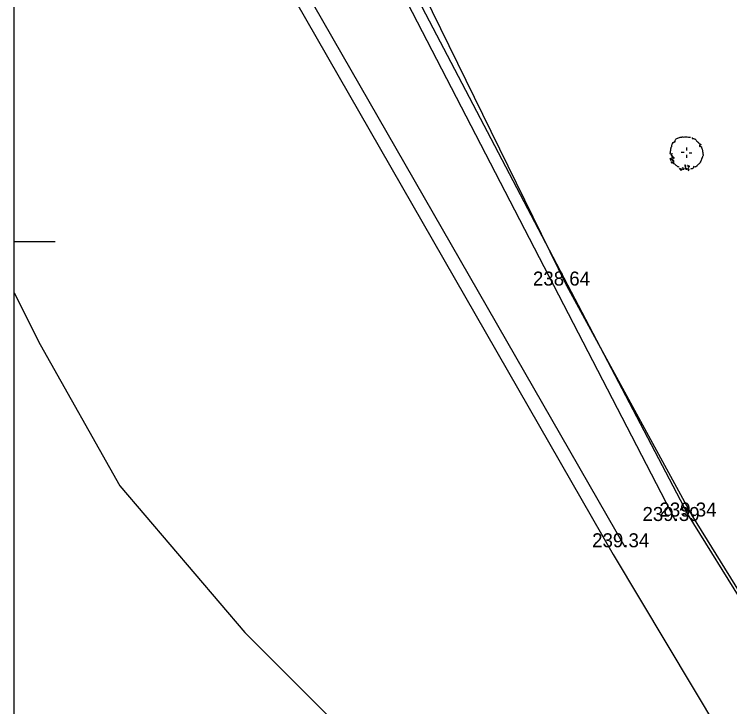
# Model space of a CAD drawing. Extents: x -601589 to -601440, y -1201842 to -1201527.
# Drawn here: x -601588.9 to -601537.6, y -1201664.9 to -1201615.4 of the extents above; entities that cross this region are included whole.
import ezdxf

# ---------------------------------------------------------------- set-up
doc = ezdxf.new("R2010")
doc.units = 0
for name, color, linetype in [('Hranice parcel', 7, 'Continuous'), ('u_hrany', 7, 'Continuous'), ('u_vysadba', 7, 'Continuous'), ('u_vyska', 7, 'Continuous'), ('x_rám', 7, 'Continuous')]:
    doc.layers.add(name, color=color, linetype=linetype)

msp = doc.modelspace()

# ---------------------------------------------------------------- linework, layer by layer
at = {"layer": 'Hranice parcel'}
for points in [[(-601445.87, -1201723.83), (-601456.99, -1201723.59), (-601475.22, -1201720.69), (-601492.39, -1201715.61), (-601519.73, -1201684.8), (-601540.64, -1201651.14), (-601563.05, -1201608.38), (-601567.44, -1201599.25)], [(-601574.75, -1201602.78), (-601570.23, -1201611.8), (-601545.97, -1201654.03), (-601525.15, -1201688.8), (-601494.52, -1201722.78), (-601477.14, -1201727.24), (-601457.13, -1201731.39), (-601443.02, -1201731.69)], [(-601588.867, -1201635.309), (-601587.01, -1201639.02), (-601581.31, -1201649.12), (-601572.35, -1201659.63), (-601536.87, -1201695.11), (-601502.76, -1201728.06), (-601494.415, -1201736.721)]]:
    msp.add_lwpolyline(points, dxfattribs=at)
at = {"layer": 'u_hrany'}
for points in [[(-601567.51, -1201596.21), (-601562.55, -1201607.8), (-601549.33, -1201634.79), (-601540.29, -1201651.32), (-601519.62, -1201684.67)], [(-601573.85, -1201602.35), (-601568.4, -1201599.72), (-601541.51, -1201651.64)], [(-601545.11, -1201653.52), (-601569.35, -1201611.33), (-601573.85, -1201602.35)]]:
    msp.add_lwpolyline(points, dxfattribs=at)
at = {"layer": 'u_vysadba'}
for points in [[(-601541.707, -1201624.584), (-601541.706, -1201624.555), (-601541.646, -1201624.529), (-601541.616, -1201624.516), (-601541.586, -1201624.503), (-601541.556, -1201624.504), (-601541.527, -1201624.506), (-601541.54, -1201624.476), (-601541.553, -1201624.446), (-601541.536, -1201624.403), (-601541.52, -1201624.36), (-601541.488, -1201624.318), (-601541.457, -1201624.29), (-601541.427, -1201624.262), (-601541.381, -1201624.236), (-601541.337, -1201624.238), (-601541.307, -1201624.21), (-601541.232, -1201624.185), (-601541.173, -1201624.173), (-601541.128, -1201624.161), (-601541.07, -1201624.164), (-601541.025, -1201624.152), (-601540.982, -1201624.154), (-601540.908, -1201624.158), (-601540.835, -1201624.147), (-601540.762, -1201624.151), (-601540.674, -1201624.156), (-601540.586, -1201624.16), (-601540.513, -1201624.164), (-601540.47, -1201624.181), (-601540.442, -1201624.197)], [(-601540.295, -1201624.19), (-601540.311, -1201624.219), (-601540.313, -1201624.248), (-601540.329, -1201624.276), (-601540.284, -1201624.264), (-601540.255, -1201624.266), (-601540.226, -1201624.267), (-601540.183, -1201624.284), (-601540.139, -1201624.287), (-601540.097, -1201624.318), (-601540.069, -1201624.349), (-601540.042, -1201624.394), (-601540, -1201624.426), (-601539.944, -1201624.473), (-601539.903, -1201624.519), (-601539.875, -1201624.549), (-601539.834, -1201624.61), (-601539.777, -1201624.642), (-601539.735, -1201624.674), (-601539.692, -1201624.691), (-601539.694, -1201624.72)], [(-601541.707, -1201624.584), (-601541.708, -1201624.599), (-601541.754, -1201624.64), (-601541.785, -1201624.668), (-601541.787, -1201624.712), (-601541.789, -1201624.756), (-601541.792, -1201624.814), (-601541.809, -1201624.857), (-601541.825, -1201624.886), (-601541.842, -1201624.914), (-601541.859, -1201624.972), (-601541.861, -1201625.001), (-601541.864, -1201625.059), (-601541.866, -1201625.103), (-601541.868, -1201625.132), (-601541.886, -1201625.205), (-601541.903, -1201625.248), (-601541.906, -1201625.291), (-601541.922, -1201625.32), (-601541.909, -1201625.35), (-601541.866, -1201625.367), (-601541.776, -1201625.342), (-601541.746, -1201625.329), (-601541.779, -1201625.386), (-601541.809, -1201625.414), (-601541.826, -1201625.442), (-601541.828, -1201625.486), (-601541.799, -1201625.487), (-601541.755, -1201625.49), (-601541.742, -1201625.52), (-601541.759, -1201625.563), (-601541.775, -1201625.591), (-601541.777, -1201625.635), (-601541.78, -1201625.679)], [(-601540.708, -1201625.126), (-601540.697, -1201624.921)], [(-601539.694, -1201624.72), (-601539.738, -1201624.732), (-601539.783, -1201624.745), (-601539.799, -1201624.773), (-601539.786, -1201624.803), (-601539.759, -1201624.848), (-601539.729, -1201624.835), (-601539.684, -1201624.823), (-601539.657, -1201624.854), (-601539.644, -1201624.884), (-601539.645, -1201624.913), (-601539.619, -1201624.973), (-601539.607, -1201625.017), (-601539.594, -1201625.062), (-601539.568, -1201625.107), (-601539.569, -1201625.137), (-601539.571, -1201625.18), (-601539.573, -1201625.21), (-601539.561, -1201625.254), (-601539.549, -1201625.313), (-601539.552, -1201625.372), (-601539.541, -1201625.431), (-601539.542, -1201625.46), (-601539.544, -1201625.489), (-601539.546, -1201625.533), (-601539.577, -1201625.561), (-601539.578, -1201625.59), (-601539.595, -1201625.633), (-601539.612, -1201625.662), (-601539.658, -1201625.703), (-601539.661, -1201625.761), (-601539.678, -1201625.819), (-601539.697, -1201625.891), (-601539.744, -1201625.947), (-601539.777, -1201626.019), (-601539.809, -1201626.076), (-601539.869, -1201626.102), (-601539.9, -1201626.129), (-601539.946, -1201626.171), (-601539.977, -1201626.213), (-601539.994, -1201626.256), (-601540.054, -1201626.282), (-601540.099, -1201626.295), (-601540.129, -1201626.308), (-601540.172, -1201626.291), (-601540.215, -1201626.274), (-601540.232, -1201626.317), (-601540.25, -1201626.375), (-601540.266, -1201626.418), (-601540.311, -1201626.43), (-601540.355, -1201626.428)], [(-601540.891, -1201625.277), (-601541.096, -1201625.266)], [(-601540.724, -1201625.433), (-601540.735, -1201625.637)], [(-601540.541, -1201625.296), (-601540.336, -1201625.292)], [(-601541.911, -1201625.672), (-601541.898, -1201625.702), (-601541.886, -1201625.746), (-601541.873, -1201625.776), (-601541.874, -1201625.806), (-601541.846, -1201625.822), (-601541.815, -1201625.794), (-601541.769, -1201625.753), (-601541.798, -1201625.751), (-601541.84, -1201625.719), (-601541.883, -1201625.703)], [(-601541.821, -1201625.911), (-601541.811, -1201625.999), (-601541.767, -1201626.002), (-601541.738, -1201626.003), (-601541.694, -1201625.991), (-601541.751, -1201625.973), (-601541.795, -1201625.971), (-601541.808, -1201625.941)], [(-601541.753, -1201625.739), (-601541.712, -1201625.785), (-601541.67, -1201625.831), (-601541.628, -1201625.862)], [(-601541.628, -1201625.862), (-601541.657, -1201625.861), (-601541.687, -1201625.859), (-601541.716, -1201625.858), (-601541.729, -1201625.828), (-601541.727, -1201625.799), (-601541.74, -1201625.769)], [(-601541.729, -1201625.55), (-601541.731, -1201625.593), (-601541.718, -1201625.623), (-601541.706, -1201625.668), (-601541.693, -1201625.698), (-601541.663, -1201625.7), (-601541.647, -1201625.671), (-601541.587, -1201625.645), (-601541.63, -1201625.628), (-601541.659, -1201625.612), (-601541.716, -1201625.58)], [(-601541.257, -1201626.321), (-601541.3, -1201626.304), (-601541.329, -1201626.288), (-601541.358, -1201626.287), (-601541.385, -1201626.241), (-601541.413, -1201626.225), (-601541.455, -1201626.194), (-601541.498, -1201626.177), (-601541.54, -1201626.131), (-601541.568, -1201626.1), (-601541.639, -1201626.067), (-601541.637, -1201626.023), (-601541.634, -1201625.979), (-601541.647, -1201625.949), (-601541.676, -1201625.933), (-601541.644, -1201625.891), (-601541.615, -1201625.892)], [(-601541.246, -1201626.381), (-601541.15, -1201626.503), (-601541.123, -1201626.548), (-601541.091, -1201626.506), (-601541.09, -1201626.477), (-601541.118, -1201626.46), (-601541.161, -1201626.444), (-601541.189, -1201626.427), (-601541.218, -1201626.411)], [(-601541.023, -1201626.334), (-601541.027, -1201626.407), (-601541.015, -1201626.451), (-601540.987, -1201626.482), (-601540.928, -1201626.471), (-601540.897, -1201626.443), (-601540.91, -1201626.413), (-601540.954, -1201626.396), (-601540.997, -1201626.379)], [(-601540.853, -1201626.152), (-601540.842, -1201626.226), (-601540.815, -1201626.271), (-601540.771, -1201626.259), (-601540.769, -1201626.23), (-601540.767, -1201626.201), (-601540.811, -1201626.184), (-601540.839, -1201626.168)], [(-601540.818, -1201626.33), (-601540.734, -1201626.408), (-601540.706, -1201626.424), (-601540.693, -1201626.454), (-601540.724, -1201626.481), (-601540.753, -1201626.48), (-601540.766, -1201626.45), (-601540.793, -1201626.404), (-601540.821, -1201626.374)], [(-601540.65, -1201626.192), (-601540.624, -1201626.252), (-601540.612, -1201626.297), (-601540.584, -1201626.328), (-601540.554, -1201626.315), (-601540.522, -1201626.272), (-601540.521, -1201626.243), (-601540.565, -1201626.241), (-601540.593, -1201626.225), (-601540.621, -1201626.209), (-601540.651, -1201626.207)], [(-601540.619, -1201626.443), (-601540.608, -1201626.517), (-601540.595, -1201626.547), (-601540.565, -1201626.534), (-601540.534, -1201626.491), (-601540.562, -1201626.461), (-601540.59, -1201626.444), (-601540.619, -1201626.443)], [(-601540.355, -1201626.428), (-601540.399, -1201626.44), (-601540.43, -1201626.468)]]:
    msp.add_lwpolyline(points, dxfattribs=at)
at = {"layer": 'x_rám'}
msp.add_line((-601585.933, -1201631.653), (-601588.867, -1201631.653), dxfattribs=at)
msp.add_lwpolyline([(-601440.367, -1201526.653), (-601440.367, -1201841.653), (-601588.867, -1201841.653), (-601588.867, -1201526.653)], close=True, dxfattribs=at)

# ---------------------------------------------------------------- texts
at = {"layer": 'u_vyska'}
for s, p in [('238.64', (-601551.723, -1201634.79)), ('239.34', (-601542.664, -1201651.32)), ('239.39', (-601543.878, -1201651.64)), ('239.34', (-601547.484, -1201653.52))]:
    msp.add_text(s, height=1, dxfattribs=at).set_placement(p)

doc.saveas('drawing.dxf')
